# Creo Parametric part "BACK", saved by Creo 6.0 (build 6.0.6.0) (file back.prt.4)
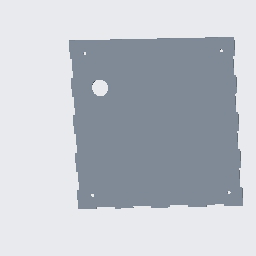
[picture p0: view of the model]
Units: Inch lbm Second (Pro/E Default); INCH, POUND, SECS

Created from: INLBS_PART_SOLID.PRT

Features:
  1. datum plane "RIGHT"
  2. datum plane "TOP"
  3. datum plane "FRONT"
  4. coordinate system
  5. sketch "Sketch 1"
  6. extrusion "Extrude 1"
  7. sketch "Sketch 3"
  8. sketch "Sketch 4"
  9. extruded cut "Extrude 3"
  10. sketch "Sketch 5"
  11. extruded cut "Extrude 4"

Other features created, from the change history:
  extruded cut "Extrude 2"
  sketch "Sketch 4"
  extruded cut "Extrude 3"

Surfaces: 54 plane, 5 cylinder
